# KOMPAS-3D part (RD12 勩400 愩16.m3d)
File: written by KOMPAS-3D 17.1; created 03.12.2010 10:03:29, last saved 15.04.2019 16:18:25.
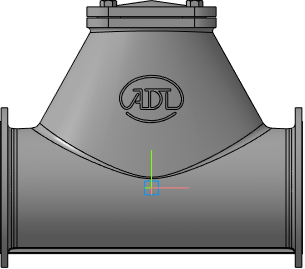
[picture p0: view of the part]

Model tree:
1. Плоскость XY
2. Плоскость ZX
3. Плоскость ZY
4. Ось X
5. Ось Y
6. Ось Z
7. Начало координат
8. Операция без истории:2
